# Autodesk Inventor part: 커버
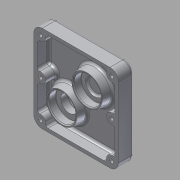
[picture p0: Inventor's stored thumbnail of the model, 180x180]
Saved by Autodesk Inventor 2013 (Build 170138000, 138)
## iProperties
Created: 2015-10
Part Number: 커버
Material: 알루미늄 6061
Document SubType Name: Modeling
Designer: mduedu
Density: 2.71 g/cm^3
Mass: 254.004 g
Surface Area: 401.286 cm^2
Volume: 93.7284 cm^3
Author: mduedu
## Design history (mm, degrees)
sketch "스케치1"
  geometry: L1 (-50, -51.5)-(50, -51.5); L2 (50, -51.5)-(50, 51.5); L3 (50, 51.5)-(-50, 51.5); L4 (-50, 51.5)-(-50, -51.5); L5 (-50, -51.5)-(50, 51.5); L6 (50, -51.5)-(-50, 51.5); 1 further point
  constraints: 12 end point, 2 midpoint, 2 parallel, 1 horizontal, 1 perpendicular
  dimensions: "d0" = 100 distance of L3.end L2.end; "d1" = 103 distance of L2.end L1.end
extrude "돌출1" new body sketch "스케치1" distance "d2" = 18; taper "d3" = 0 deg
fillet "모깎기1" dims "d4" = 10
fillet "모깎기2" dims "d5" = 3
feature "쉘1" dims "d6" = 4
sketch "스케치2"
  geometry: L1 (40, 51.5)-(-40, 51.5) reference; L2 (50, -41.5)-(50, 41.5) reference; L3 (-40, -51.5)-(40, -51.5) reference; L4 (-50, 41.5)-(-50, -41.5) reference; L5 (-50, 0)-(50, 0); L6 (0, 51.5)-(0, -51.5); C1 r 6 at (-42, 43.5); C2 r 6 at (-42, 0); C3 r 6 at (-42, -43.5); C4 r 6 at (42, -43.5); C5 r 6 at (42, 0); C6 r 6 at (42, 43.5); 1 further point
  constraints: 6 centre point, 4 end point, 4 midpoint, 4 symmetric about line, 1 equal radius, 1 point on line, 1 vertical alignment, 4 other
  dimensions: "d7" = 12 diameter of C1; "d8" = 8 distance from line of C1.centre L1; "d9" = 8 distance from line of C1.centre L4
extrude "돌출2" join sketch "스케치2" stored distance "d10" = 0; taper "d11" = 0 deg
fillet "모깎기3" dims "d12" = 3
fillet "모깎기4" dims "d13" = 3
sketch "스케치3"
  geometry: A1 r 6 centre (42, 43.5) between (36.037, 44.167) and (42.667, 37.537) reference; A2 r 6 centre (42, 0) between (42.667, 5.963) and (42.667, -5.963) reference; A3 r 6 centre (42, -43.5) between (42.667, -37.537) and (36.037, -44.167) reference; A4 r 6 centre (-42, -43.5) between (-36.037, -44.167) and (-42.667, -37.537) reference; A5 r 6 centre (-42, 0) between (-42.667, -5.963) and (-42.667, 5.963) reference; A6 r 6 centre (-42, 43.5) between (-42.667, 37.537) and (-36.037, 44.167) reference; 7 further points
  constraints: 6 coincident
hole "구멍1" sketch "스케치3" at (-42, 43.5), (-42, 0), (-42, -43.5), (42, -43.5), (42, 0), (42, 43.5) diameter "d14" = 4.5; stored, may be unused: countersink angle "d18" = 90 deg, drill point angle "d20" = 118 deg; dims "d15" = 6, "d16" = 8, "d17" = 4.4, "d19" = 8
sketch "스케치4"
  geometry: L1 (83.056, 3)-(83.056, 86) reference; L2 (73.056, 96)-(-6.944, 96) reference; C1 r 20 at (43.056, 56); 1 further point
  constraints: 1 centre point
  dimensions: "d21" = 40 diameter of C1; "d22" = 40 distance from line of C1.centre L1; "d23" = 40 distance from line of C1.centre L2
extrude "돌출3" join sketch "스케치4" distance "d24" = 11; taper "d25" = -10 deg
hole "구멍2" diameter "d28" = 22; stored, may be unused: countersink angle "d32" = 90 deg, drill point angle "d34" = 0 deg; dims "d29" = 6, "d30" = 32, "d31" = 9, "d33" = 11, "d35" = 10, "d36" = 10
sketch "스케치5"
  geometry: L1 (-40, -51.5)-(40, -51.5) reference; L2 (50, -41.5)-(50, 41.5) reference; C1 r 25 at (20, -21.5); 1 further point
  constraints: 1 centre point
  dimensions: "d37" = 50 diameter of C1; "d40" = 30 distance from line of C1.centre L1; "d41" = 30 distance from line of C1.centre L2
extrude "돌출4" join sketch "스케치5" distance "d42" = 15; taper "d43" = -10 deg
sketch "스케치6"
  geometry: C1 r 25 at (13.056, 23) reference; C2 r 20 at (13.056, 23); 1 further point
  constraints: 1 centre point, 1 coincident
  dimensions: "d44" = 40 diameter of C2
extrude "돌출5" join sketch "스케치6" distance "d45" = 11; taper "d46" = -10 deg
hole "구멍3" diameter "d49" = 20; stored, may be unused: countersink angle "d53" = 90 deg, drill point angle "d55" = 118 deg; dims "d47" = 10, "d48" = 10, "d50" = 6, "d51" = 32, "d52" = 9, "d54" = 11
hole "구멍4" diameter "d58" = 24; stored, may be unused: countersink angle "d62" = 90 deg, drill point angle "d64" = 0 deg; dims "d56" = 10, "d57" = 10, "d59" = 6, "d60" = 28, "d61" = 11, "d63" = 13
chamfer "모따기1" distance "d65" = 1; stored, may be unused: second distance "d66" = 2, angle "d67" = 45 deg
sketch "스케치7" dims "d68" = 36
  geometry: C1 r 25 at (0, 0) reference; 3 further points
  constraints: 2 vertical alignment, 1 coincident, 2 other
hole "구멍5" sketch "스케치7" at (0, 18) diameter "d69" = 2.459; stored, may be unused: countersink angle "d73" = 90 deg, drill point angle "d75" = 118 deg; dims "d70" = 8, "d71" = 28, "d72" = 11, "d74" = 10
sketch "스케치8"
  geometry: L1 (-50, 41.5)-(-50, -41.5) reference; L2 (40, 51.5)-(-40, 51.5) reference; 2 further points
  constraints: 1 other
  dimensions: "d79" = 50 distance from line of point (0, 26.5) L1; "d80" = 25 distance from line of point (0, 26.5) L2
feature "엠보싱1" sketch "스케치8" dims "d0" = 100, "d1" = 103, "d5" = 3, "d81" = 0.5, "d82" = 0
fillet "모깎기5" dims "d83" = 3
fillet "모깎기6" dims "d84" = 3
fillet "모깎기7" dims "d85" = 3
fillet "모깎기8" dims "d86" = 0.3
fillet "모깎기9" dims "d87" = 3
node "솔리드1"
pattern_circular "원형 패턴1" dims angle "d77" = 360 deg
